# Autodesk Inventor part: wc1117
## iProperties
Shininess: 64.0
Length Units: 11272
Angle Units: 11279
Time Units: 11290
Mass Units: 11286
Length Display Precision: 3
Angle Display Precision: 2
Compacted: True
Part Number: wc1117
Document SubType Name: Modeling
Created: 2004-08
Designer: John Blackburn
Manufacturer: Standard
Standards Organization: Custom
Material: Phenolic
Density: 0.0
Volumn: 0.0
Area: 0.0
PropertySet Name: Model Information
Control State: 0
Master: False
Checked Out: False
Author: John Blackburn
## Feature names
1. Base1
